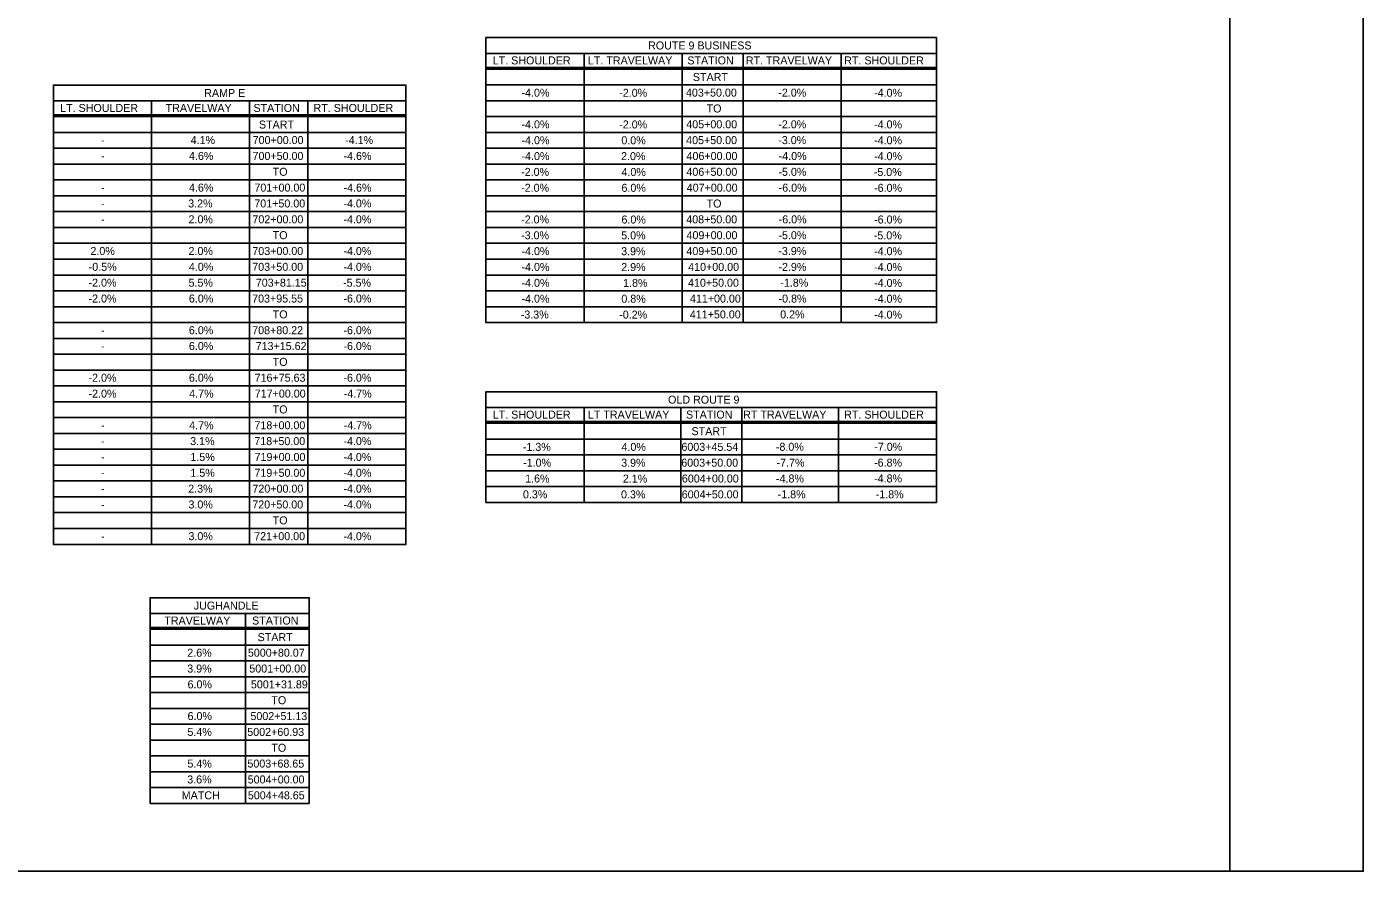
# Model space of a CAD drawing. Extents: x -15319374 to 1762012, y 465773 to 3693661.
# Drawn here: x -15314166 to -15313664, y 3691328 to 3691645 of the extents above; entities that cross this region are included whole.
import ezdxf

# ---------------------------------------------------------------- set-up
doc = ezdxf.new("R2010")
doc.units = 0
doc.layers.add('BORDER', color=7, linetype='Continuous')
doc.layers.add('DIMENSIONS', color=7, linetype='Continuous')

msp = doc.modelspace()

# ---------------------------------------------------------------- linework, layer by layer
at = {"layer": 'BORDER'}
for p, q in [((-15313714.43, 3691328.02), (-15313714.43, 3691853.02)), ((-15313956.57, 3691634.81), (-15313956.57, 3691539.79)), ((-15313919.81, 3691634.81), (-15313919.81, 3691539.79)), ((-15313896.93, 3691634.81), (-15313896.93, 3691539.79)), ((-15313860.16, 3691634.81), (-15313860.16, 3691539.79)), ((-15313860.16, 3691634.81), (-15313860.16, 3691539.79)), ((-15313993.34, 3691629.53), (-15313824.4, 3691629.53)), ((-15313993.34, 3691628.93), (-15313824.4, 3691628.93)), ((-15313993.34, 3691622.99), (-15313824.4, 3691622.99)), ((-15313993.34, 3691622.99), (-15313824.4, 3691622.99)), ((-15313993.34, 3691622.99), (-15313824.4, 3691622.99)), ((-15314155.52, 3691616.98), (-15314155.52, 3691498.78)), ((-15314118.75, 3691616.98), (-15314118.75, 3691450.65)), ((-15314081.98, 3691616.98), (-15314081.98, 3691450.65)), ((-15314060.11, 3691616.98), (-15314060.11, 3691450.65)), ((-15313993.34, 3691617.05), (-15313824.4, 3691617.05)), ((-15314155.52, 3691611.7), (-15314023.34, 3691611.7)), ((-15314155.52, 3691611.1), (-15314023.34, 3691611.1)), ((-15313993.34, 3691611.1), (-15313824.4, 3691611.1)), ((-15314155.52, 3691605.16), (-15314023.34, 3691605.16)), ((-15314155.52, 3691605.16), (-15314023.34, 3691605.16)), ((-15314155.52, 3691605.16), (-15314023.34, 3691605.16)), ((-15313993.34, 3691605.16), (-15313824.4, 3691605.16)), ((-15314155.52, 3691599.22), (-15314023.34, 3691599.22)), ((-15313993.34, 3691599.22), (-15313824.4, 3691599.22)), ((-15314155.52, 3691593.28), (-15314023.34, 3691593.28)), ((-15313993.34, 3691593.28), (-15313824.4, 3691593.28)), ((-15314155.52, 3691587.33), (-15314023.34, 3691587.33)), ((-15313993.34, 3691587.33), (-15313824.4, 3691587.33)), ((-15314155.52, 3691581.39), (-15314023.34, 3691581.39)), ((-15313993.34, 3691581.39), (-15313824.4, 3691581.39)), ((-15314155.52, 3691575.45), (-15314023.34, 3691575.45)), ((-15313993.34, 3691575.45), (-15313824.4, 3691575.45)), ((-15314155.52, 3691569.5), (-15314023.34, 3691569.5)), ((-15313993.34, 3691569.5), (-15313824.4, 3691569.5)), ((-15314155.52, 3691563.56), (-15314023.34, 3691563.56)), ((-15313993.34, 3691563.56), (-15313824.4, 3691563.56)), ((-15314155.52, 3691557.62), (-15314023.34, 3691557.62)), ((-15313993.34, 3691557.62), (-15313824.4, 3691557.62)), ((-15314155.52, 3691551.68), (-15314023.34, 3691551.68)), ((-15313993.34, 3691551.68), (-15313824.4, 3691551.68)), ((-15314155.52, 3691545.73), (-15314023.34, 3691545.73)), ((-15313993.34, 3691545.73), (-15313824.4, 3691545.73)), ((-15314155.52, 3691539.79), (-15314023.34, 3691539.79)), ((-15313993.34, 3691539.79), (-15313824.4, 3691539.79)), ((-15313956.57, 3691539.79), (-15313956.57, 3691533.85)), ((-15313919.81, 3691539.79), (-15313919.81, 3691533.85)), ((-15313896.93, 3691539.79), (-15313896.93, 3691533.85)), ((-15313860.16, 3691539.79), (-15313860.16, 3691533.85)), ((-15314155.52, 3691533.85), (-15314023.34, 3691533.85)), ((-15313993.34, 3691533.85), (-15313824.4, 3691533.85)), ((-15314155.52, 3691527.91), (-15314023.34, 3691527.91)), ((-15314155.52, 3691521.96), (-15314023.34, 3691521.96)), ((-15314155.52, 3691516.02), (-15314023.34, 3691516.02)), ((-15314155.52, 3691510.08), (-15314023.34, 3691510.08)), ((-15314155.52, 3691504.13), (-15314023.34, 3691504.13)), ((-15313956.57, 3691501.96), (-15313956.57, 3691466.37)), ((-15313920.31, 3691501.96), (-15313920.31, 3691466.37)), ((-15313897.43, 3691501.96), (-15313897.43, 3691466.37)), ((-15313861.16, 3691501.96), (-15313861.16, 3691466.37)), ((-15314155.52, 3691498.19), (-15314023.34, 3691498.19)), ((-15313993.34, 3691496.68), (-15313824.4, 3691496.68)), ((-15313993.34, 3691496.09), (-15313824.4, 3691496.09)), ((-15314155.52, 3691492.25), (-15314023.34, 3691492.25)), ((-15313993.34, 3691490.14), (-15313824.4, 3691490.14)), ((-15313993.34, 3691490.14), (-15313824.4, 3691490.14)), ((-15313993.34, 3691490.14), (-15313824.4, 3691490.14)), ((-15314155.52, 3691486.31), (-15314023.34, 3691486.31)), ((-15313993.34, 3691484.2), (-15313824.4, 3691484.2)), ((-15314155.52, 3691480.36), (-15314023.34, 3691480.36)), ((-15314155.52, 3691474.42), (-15314023.34, 3691474.42)), ((-15313993.34, 3691478.26), (-15313824.4, 3691478.26)), ((-15313993.34, 3691472.31), (-15313824.4, 3691472.31)), ((-15314155.52, 3691468.48), (-15314023.34, 3691468.48)), ((-15313993.34, 3691466.37), (-15313824.4, 3691466.37)), ((-15314155.52, 3691462.54), (-15314023.34, 3691462.54)), ((-15314155.52, 3691456.59), (-15314023.34, 3691456.59)), ((-15314119.25, 3691424.71), (-15314119.25, 3691353.46)), ((-15314083.48, 3691424.71), (-15314083.48, 3691353.46)), ((-15314059.61, 3691424.71), (-15314059.61, 3691353.46)), ((-15314119.25, 3691419.43), (-15314059.61, 3691419.43)), ((-15314119.25, 3691418.83), (-15314059.61, 3691418.83)), ((-15314119.25, 3691412.89), (-15314059.61, 3691412.89)), ((-15314119.25, 3691412.89), (-15314059.61, 3691412.89)), ((-15314119.25, 3691412.89), (-15314059.61, 3691412.89)), ((-15314119.25, 3691406.95), (-15314059.61, 3691406.95)), ((-15314119.25, 3691401), (-15314059.61, 3691401)), ((-15314119.25, 3691395.06), (-15314059.61, 3691395.06)), ((-15314119.25, 3691389.12), (-15314059.61, 3691389.12)), ((-15314119.25, 3691383.17), (-15314059.61, 3691383.17)), ((-15314119.25, 3691377.23), (-15314059.61, 3691377.23)), ((-15314119.25, 3691371.29), (-15314059.61, 3691371.29)), ((-15314119.25, 3691365.35), (-15314059.61, 3691365.35)), ((-15314119.25, 3691359.4), (-15314059.61, 3691359.4))]:
    msp.add_line(p, q, dxfattribs=at)
for points in [[(-15314464.43, 3691853.02), (-15313664.43, 3691853.02), (-15313664.43, 3691328.02), (-15314464.43, 3691328.02)], [(-15313993.34, 3691634.81), (-15313824.4, 3691634.81), (-15313824.4, 3691533.85), (-15313993.34, 3691533.85)], [(-15314155.52, 3691616.98), (-15314023.34, 3691616.98), (-15314023.34, 3691450.65), (-15314155.52, 3691450.65)], [(-15313993.34, 3691501.96), (-15313824.4, 3691501.96), (-15313824.4, 3691466.37), (-15313993.34, 3691466.37)], [(-15314119.25, 3691424.71), (-15314059.61, 3691424.71), (-15314059.61, 3691353.46), (-15314119.25, 3691353.46)]]:
    msp.add_lwpolyline(points, close=True, dxfattribs=at)
for points in [[(-15313993.34, 3691634.81), (-15313993.34, 3691640.75), (-15313824.4, 3691640.75), (-15313824.4, 3691634.81)], [(-15314155.52, 3691616.98), (-15314155.52, 3691622.92), (-15314023.34, 3691622.92), (-15314023.34, 3691616.98)], [(-15313993.34, 3691501.96), (-15313993.34, 3691507.91), (-15313824.4, 3691507.91), (-15313824.4, 3691501.96)], [(-15314119.25, 3691424.71), (-15314119.25, 3691430.65), (-15314059.61, 3691430.65), (-15314059.61, 3691424.71)]]:
    msp.add_lwpolyline(points, dxfattribs=at)

# ---------------------------------------------------------------- texts
at = {"layer": 'DIMENSIONS'}
for s, p in [('ROUTE 9 BUSINESS', (-15313932.56, 3691636.28)), ('LT. SHOULDER', (-15313990.79, 3691630.67)), ('LT. TRAVELWAY', (-15313955.12, 3691630.67)), ('STATION', (-15313917.84, 3691630.67)), ('RT. TRAVELWAY', (-15313895.91, 3691630.67)), ('RT. SHOULDER', (-15313859.04, 3691630.67)), ('START', (-15313915.77, 3691624.44)), ('RAMP E', (-15314098.97, 3691618.45)), ('-4.0%', (-15313980.01, 3691618.56)), ('-2.0%', (-15313943.38, 3691618.53)), ('403+50.00', (-15313918.36, 3691618.59)), ('-2.0%', (-15313883.74, 3691618.59)), ('-4.0%', (-15313847.83, 3691618.53)), ('LT. SHOULDER', (-15314152.97, 3691612.84)), ('TRAVELWAY', (-15314113.43, 3691612.84)), ('STATION', (-15314080.52, 3691612.84)), ('RT. SHOULDER', (-15314057.98, 3691612.84)), ('TO', (-15313910.61, 3691612.65)), ('START', (-15314078.45, 3691606.62)), ('-4.0%', (-15313980.01, 3691606.68)), ('-2.0%', (-15313943.38, 3691606.65)), ('405+00.00', (-15313918.24, 3691606.71)), ('-2.0%', (-15313883.74, 3691606.71)), ('-4.0%', (-15313847.83, 3691606.65)), ('-', (-15314137.64, 3691600.79)), ('4.1%', (-15314104.05, 3691600.79)), ('700+00.00', (-15314080.8, 3691600.79)), ('-4.1%', (-15314046.12, 3691600.79)), ('-4.0%', (-15313980.01, 3691600.73)), ('0.0%', (-15313942.58, 3691600.71)), ('405+50.00', (-15313918.29, 3691600.77)), ('-3.0%', (-15313883.76, 3691600.77)), ('-4.0%', (-15313847.83, 3691600.71)), ('-', (-15314137.64, 3691594.84)), ('4.6%', (-15314104.67, 3691594.84)), ('700+50.00', (-15314080.85, 3691594.84)), ('-4.6%', (-15314046.73, 3691594.84)), ('-4.0%', (-15313980.01, 3691594.79)), ('2.0%', (-15313942.68, 3691594.76)), ('406+00.00', (-15313918.14, 3691594.82)), ('-4.0%', (-15313883.6, 3691594.82)), ('-4.0%', (-15313847.83, 3691594.76)), ('TO', (-15314073.29, 3691588.9)), ('-2.0%', (-15313980.15, 3691588.85)), ('4.0%', (-15313942.53, 3691588.82)), ('406+50.00', (-15313918.19, 3691588.88)), ('-5.0%', (-15313883.69, 3691588.88)), ('-5.0%', (-15313847.93, 3691588.82)), ('-', (-15314137.64, 3691582.96)), ('4.6%', (-15314104.67, 3691582.96)), ('701+00.00', (-15314080.14, 3691582.96)), ('-4.6%', (-15314046.73, 3691582.96)), ('-2.0%', (-15313980.15, 3691582.9)), ('6.0%', (-15313942.53, 3691582.88)), ('407+00.00', (-15313918.07, 3691582.94)), ('-6.0%', (-15313883.6, 3691582.94)), ('-6.0%', (-15313847.83, 3691582.88)), ('3.2%', (-15314104.97, 3691577.02)), ('701+50.00', (-15314080.18, 3691577.02)), ('-4.0%', (-15314046.78, 3691577.02)), ('TO', (-15313910.61, 3691576.99)), ('-', (-15314137.64, 3691577.02)), ('-', (-15314137.64, 3691571.07)), ('2.0%', (-15314104.85, 3691571.07)), ('702+00.00', (-15314080.89, 3691571.07)), ('-4.0%', (-15314046.78, 3691571.07)), ('-2.0%', (-15313980.15, 3691571.02)), ('6.0%', (-15313942.53, 3691570.99)), ('408+50.00', (-15313918.24, 3691571.05)), ('-6.0%', (-15313883.6, 3691571.05)), ('-6.0%', (-15313847.83, 3691570.99)), ('TO', (-15314073.29, 3691565.13)), ('-3.0%', (-15313980.17, 3691565.08)), ('5.0%', (-15313942.63, 3691565.05)), ('409+00.00', (-15313918.14, 3691565.11)), ('-5.0%', (-15313883.69, 3691565.11)), ('-5.0%', (-15313847.93, 3691565.05)), ('2.0%', (-15314141.62, 3691559.19)), ('2.0%', (-15314104.85, 3691559.19)), ('703+00.00', (-15314080.92, 3691559.19)), ('-4.0%', (-15314046.78, 3691559.19)), ('-4.0%', (-15313980.01, 3691559.13)), ('3.9%', (-15313942.65, 3691559.11)), ('409+50.00', (-15313918.19, 3691559.17)), ('-3.9%', (-15313883.72, 3691559.17)), ('-4.0%', (-15313847.83, 3691559.11)), ('-0.5%', (-15314142.28, 3691553.25)), ('4.0%', (-15314104.71, 3691553.25)), ('703+50.00', (-15314080.96, 3691553.25)), ('-4.0%', (-15314046.78, 3691553.25)), ('-4.0%', (-15313980.01, 3691553.19)), ('2.9%', (-15313942.63, 3691553.16)), ('410+00.00', (-15313917.53, 3691553.22)), ('-2.9%', (-15313883.69, 3691553.22)), ('-4.0%', (-15313847.83, 3691553.16)), ('-2.0%', (-15314142.33, 3691547.3)), ('5.5%', (-15314104.85, 3691547.3)), ('703+81.15', (-15314079.63, 3691547.3)), ('-5.5%', (-15314046.92, 3691547.3)), ('-4.0%', (-15313980.01, 3691547.25)), ('1.8%', (-15313941.92, 3691547.22)), ('410+50.00', (-15313917.58, 3691547.28)), ('-1.8%', (-15313882.98, 3691547.28)), ('-4.0%', (-15313847.83, 3691547.22)), ('-2.0%', (-15314142.33, 3691541.36)), ('6.0%', (-15314104.71, 3691541.36)), ('703+95.55', (-15314081, 3691541.36)), ('-6.0%', (-15314046.78, 3691541.36)), ('-4.0%', (-15313980.01, 3691541.31)), ('0.8%', (-15313942.58, 3691541.28)), ('411+00.00', (-15313916.87, 3691541.34)), ('-0.8%', (-15313883.65, 3691541.34)), ('-4.0%', (-15313847.83, 3691541.28)), ('TO', (-15314073.29, 3691535.42)), ('-3.3%', (-15313980.29, 3691535.36)), ('-0.2%', (-15313943.38, 3691535.34)), ('411+50.00', (-15313916.91, 3691535.4)), ('0.2%', (-15313883.03, 3691535.4)), ('-4.0%', (-15313847.83, 3691535.34)), ('-', (-15314137.64, 3691529.47)), ('6.0%', (-15314104.71, 3691529.47)), ('708+80.22', (-15314080.98, 3691529.47)), ('-6.0%', (-15314046.78, 3691529.47)), ('-', (-15314137.64, 3691523.53)), ('6.0%', (-15314104.71, 3691523.53)), ('713+15.62', (-15314079.68, 3691523.53)), ('-6.0%', (-15314046.78, 3691523.53)), ('TO', (-15314073.29, 3691517.59)), ('-2.0%', (-15314142.33, 3691511.65)), ('6.0%', (-15314104.71, 3691511.65)), ('716+75.63', (-15314080.08, 3691511.65)), ('-6.0%', (-15314046.78, 3691511.65)), ('-2.0%', (-15314142.33, 3691505.7)), ('4.7%', (-15314104.59, 3691505.7)), ('717+00.00', (-15314080.02, 3691505.7)), ('-4.7%', (-15314046.66, 3691505.7)), ('OLD ROUTE 9', (-15313925.06, 3691503.43)), ('TO', (-15314073.29, 3691499.76)), ('LT. SHOULDER', (-15313990.79, 3691497.82)), ('LT TRAVELWAY', (-15313955.12, 3691497.82)), ('STATION', (-15313918.34, 3691497.82)), ('RT TRAVELWAY', (-15313896.91, 3691497.82)), ('RT. SHOULDER', (-15313859.04, 3691497.82)), ('-', (-15314137.64, 3691493.82)), ('4.7%', (-15314104.59, 3691493.82)), ('718+00.00', (-15314080.14, 3691493.82)), ('-4.7%', (-15314046.66, 3691493.82)), ('START', (-15313916.27, 3691491.6)), ('-', (-15314137.64, 3691487.88)), ('3.1%', (-15314104.22, 3691487.88)), ('718+50.00', (-15314080.18, 3691487.88)), ('-4.0%', (-15314046.78, 3691487.88)), ('1.5%', (-15314104.15, 3691481.93)), ('719+00.00', (-15314080.09, 3691481.93)), ('-4.0%', (-15314046.78, 3691481.93)), ('-1.3%', (-15313979.51, 3691485.72)), ('4.0%', (-15313942.53, 3691485.7)), ('6003+45.54', (-15313920.06, 3691485.72)), ('-8.0%', (-15313884.65, 3691485.74)), ('-7.0%', (-15313847.76, 3691485.75)), ('-', (-15314137.64, 3691481.93)), ('1.5%', (-15314104.15, 3691475.99)), ('719+50.00', (-15314080.14, 3691475.99)), ('-4.0%', (-15314046.78, 3691475.99)), ('-1.0%', (-15313979.4, 3691479.78)), ('3.9%', (-15313942.65, 3691479.76)), ('6003+50.00', (-15313920.11, 3691479.78)), ('-7.7%', (-15313884.41, 3691479.79)), ('-6.8%', (-15313847.83, 3691479.81)), ('-', (-15314137.64, 3691475.99)), ('1.6%', (-15313978.64, 3691473.84)), ('2.1%', (-15313942.01, 3691473.82)), ('6004+00.00', (-15313919.89, 3691473.84)), ('-4.8%', (-15313884.6, 3691473.85)), ('-4.8%', (-15313847.83, 3691473.87)), ('-', (-15314137.64, 3691470.05)), ('2.3%', (-15314104.97, 3691470.05)), ('720+00.00', (-15314080.89, 3691470.05)), ('-4.0%', (-15314046.78, 3691470.05)), ('0.3%', (-15313979.47, 3691467.89)), ('0.3%', (-15313942.7, 3691467.88)), ('6004+50.00', (-15313919.94, 3691467.89)), ('-1.8%', (-15313883.98, 3691467.91)), ('-1.8%', (-15313847.22, 3691467.93)), ('-', (-15314137.64, 3691464.11)), ('3.0%', (-15314104.88, 3691464.11)), ('720+50.00', (-15314080.94, 3691464.11)), ('-4.0%', (-15314046.78, 3691464.11)), ('TO', (-15314073.29, 3691458.16)), ('3.0%', (-15314104.88, 3691452.22)), ('721+00.00', (-15314080.23, 3691452.22)), ('-4.0%', (-15314046.78, 3691452.22)), ('-', (-15314137.64, 3691452.22)), ('JUGHANDLE', (-15314102.88, 3691426.18)), ('TRAVELWAY', (-15314113.93, 3691420.57)), ('STATION', (-15314081.02, 3691420.57)), ('START', (-15314078.95, 3691414.34)), ('2.6%', (-15314105.31, 3691408.51)), ('5000+80.07', (-15314082.6, 3691408.51)), ('3.9%', (-15314105.33, 3691402.57)), ('5001+00.00', (-15314082.05, 3691402.57)), ('6.0%', (-15314105.21, 3691396.63)), ('5001+31.89', (-15314081.46, 3691396.63)), ('TO', (-15314073.79, 3691390.69)), ('6.0%', (-15314105.21, 3691384.74)), ('5002+51.13', (-15314081.64, 3691384.74)), ('5.4%', (-15314105.26, 3691378.8)), ('5002+60.93', (-15314082.82, 3691378.8)), ('TO', (-15314073.79, 3691372.86)), ('5.4%', (-15314105.26, 3691366.92)), ('5003+68.65', (-15314082.77, 3691366.92)), ('3.6%', (-15314105.33, 3691360.97)), ('5004+00.00', (-15314082.67, 3691360.97)), ('MATCH', (-15314107.39, 3691355.03)), ('5004+48.65', (-15314082.61, 3691355.03))]:
    msp.add_text(s, height=3, dxfattribs=at).set_placement(p)

doc.saveas('drawing.dxf')
